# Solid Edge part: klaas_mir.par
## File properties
Last saved by: Cymax
Revision: 52
Accuracy: 0,990
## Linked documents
klaas.par
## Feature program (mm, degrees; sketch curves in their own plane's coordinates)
part copy "CopiedPart_1"
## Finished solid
Body 1: solid body, 39 faces, 96 edges, 64 vertices.
  Faces by surface: plane 23, cylinder 8, torus 8
  Edges by curve: line 56, circle 28, intersection 12
Bounding box of the edges (mm; curved faces can reach further): 1221.056 x 180.674 x 352.473, from (235.5991, 526.7275, -344.4289) to (1456.6554, 707.4018, 8.0446).
Cylindrical faces by radius (mm): R430.6294 x1, R437.3201 x1, R450.6294 x1, R457.3201 x1, R658.028 x2, R678.028 x2
Toroidal faces (ring radius, tube radius in mm): R478.028 r180 x4, R478.028 r200 x4
Planar faces by outward normal: +x 6, -x 6, oblique 11
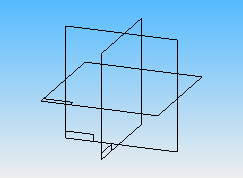
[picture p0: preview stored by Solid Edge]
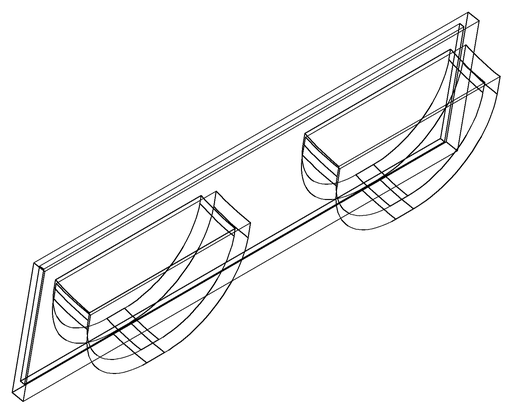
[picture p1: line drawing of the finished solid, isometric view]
